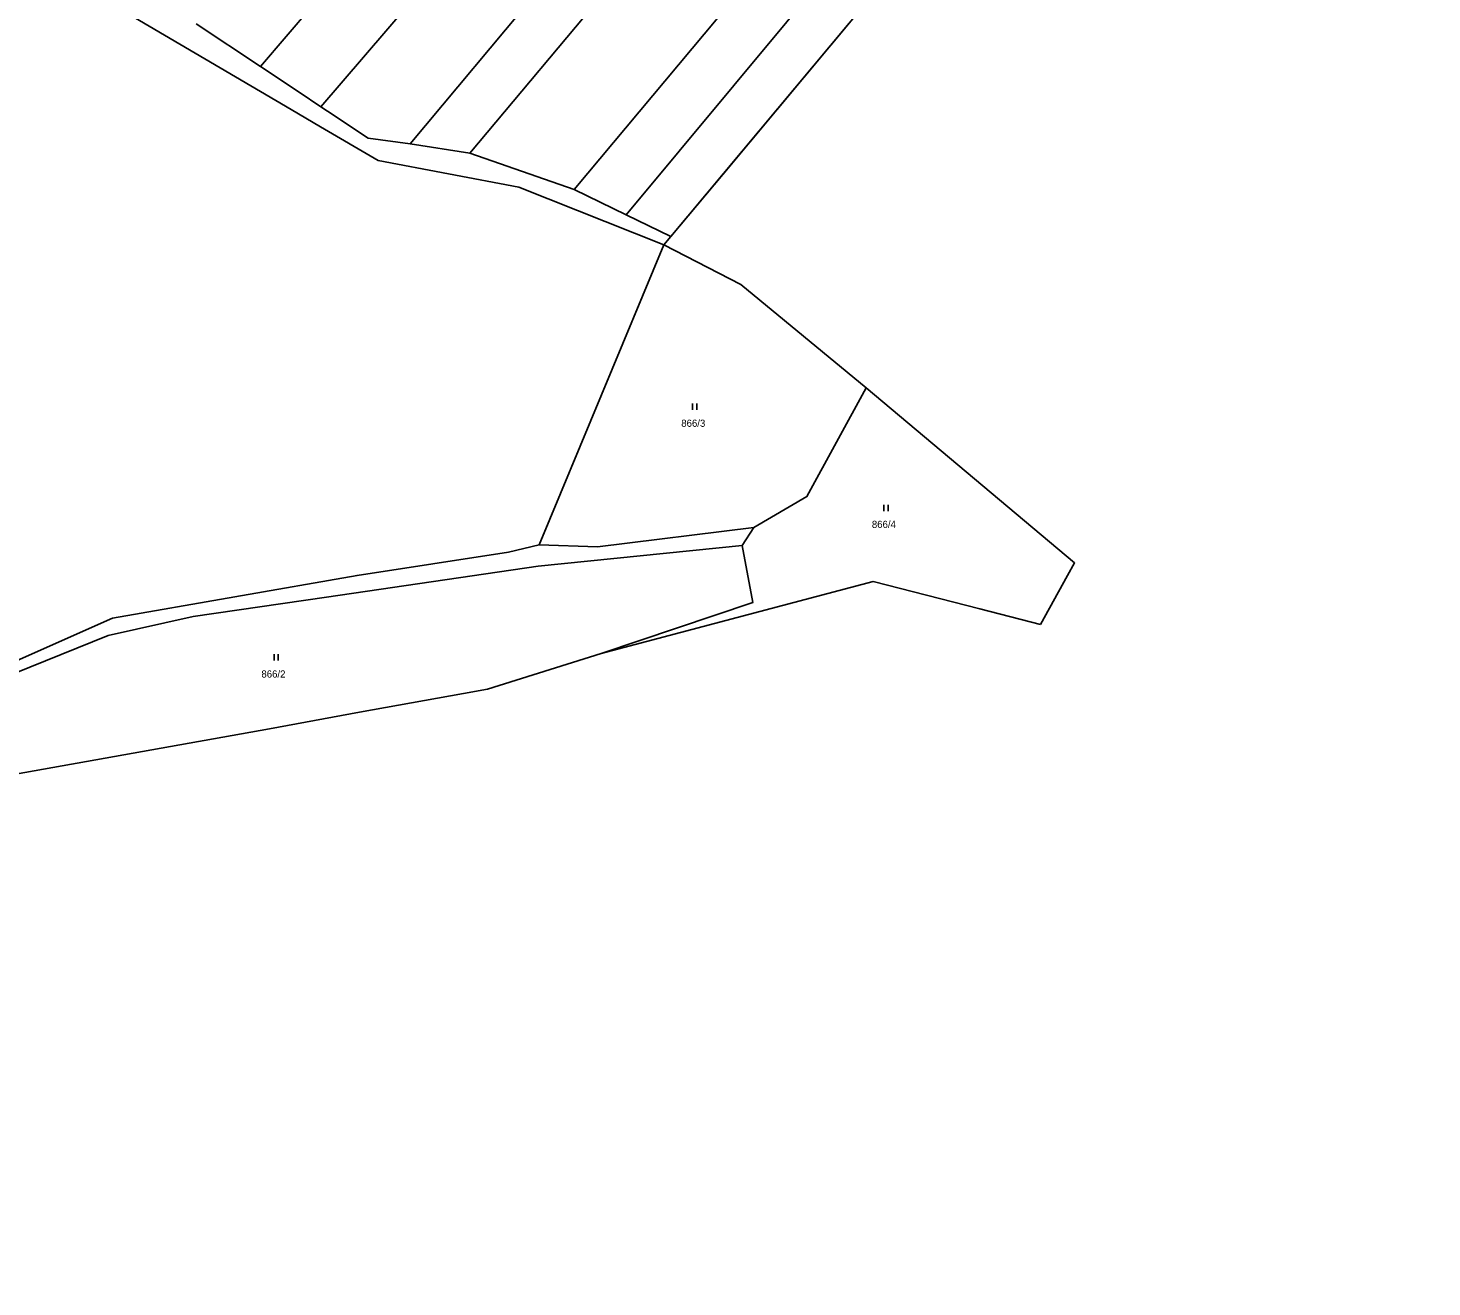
# Model space of a CAD drawing. Extents: x -7476540 to -746055, y -11317203 to -1129777.
# Drawn here: x -747223.3 to -746891.2, y -1132213.1 to -1131915.2 of the extents above; entities that cross this region are included whole.
import ezdxf

# ---------------------------------------------------------------- set-up
doc = ezdxf.new("R2010")
doc.units = 0
for name, color, linetype in [('Hranice parcel', 7, 'Continuous'), ('Parcelní čísla', 7, 'Continuous'), ('Vrstva 55', 7, 'Continuous'), ('Značky kultur', 7, 'Continuous')]:
    doc.layers.add(name, color=color, linetype=linetype)

msp = doc.modelspace()

# ---------------------------------------------------------------- linework, layer by layer
at = {"layer": 'Hranice parcel'}
for p, q in [((-747168.35, -1131924.28), (-747183.54, -1131914.17)), ((-747118.82, -1131944.76), (-747132.91, -1131942.59)), ((-747094.15, -1131953.41), (-747118.82, -1131944.76)), ((-747081.82, -1131959.38), (-747094.15, -1131953.41)), ((-747071.24, -1131964.51), (-747081.82, -1131959.38)), ((-747072.89, -1131966.47), (-747071.24, -1131964.51)), ((-747102.43, -1132037.5), (-747072.89, -1131966.47)), ((-747025.04, -1132000.35), (-747039.86, -1131988.12)), ((-747054.35, -1132037.66), (-747051.63, -1132033.4)), ((-746983.8, -1132056.28), (-746977.4, -1132044.75)), ((-746998.16, -1132052.61), (-746983.8, -1132056.28))]:
    msp.add_line(p, q, dxfattribs=at)
for points in [[(-747168.35, -1131924.28), (-747156.17, -1131910.12), (-747146.8, -1131899.23), (-747135.89, -1131886.55), (-747102.76, -1131847.44), (-747086.37, -1131828.14), (-747038.09, -1131772.55)], [(-747154.03, -1131933.81), (-747087.71, -1131856.54), (-747020.83, -1131778.66)], [(-747132.91, -1131942.59), (-747102.75, -1131906.39), (-747000.3, -1131785.93)], [(-746987.72, -1131790.65), (-747085.59, -1131905.13), (-747118.82, -1131944.76)], [(-747094.15, -1131953.41), (-747029.41, -1131875.97), (-746964.65, -1131799.29)], [(-747081.82, -1131959.38), (-747018.32, -1131883), (-746952.09, -1131804)], [(-747072.89, -1131966.47), (-747107.18, -1131952.81), (-747140.46, -1131946.56), (-747154.1, -1131938.56), (-747161.04, -1131934.49), (-747204.18, -1131909.18), (-747226.07, -1131896.73), (-747265.2, -1131885.54)], [(-747020.64, -1131903.85), (-747058.92, -1131949.83), (-747071.24, -1131964.51)], [(-747154.03, -1131933.81), (-747159.2, -1131930.37), (-747168.35, -1131924.28)], [(-747132.91, -1131942.59), (-747142.83, -1131941.27), (-747152.45, -1131934.86), (-747154.03, -1131933.81)], [(-747039.86, -1131988.12), (-747054.69, -1131975.89), (-747072.89, -1131966.47)], [(-747051.63, -1132033.4), (-747039.08, -1132026.03), (-747025.04, -1132000.35)], [(-746977.4, -1132044.75), (-746975.74, -1132041.76), (-747025.04, -1132000.35)], [(-747051.63, -1132033.4), (-747088.58, -1132037.93), (-747102.43, -1132037.5)], [(-747299.75, -1132213.05), (-747296.34, -1132200.82), (-747282.88, -1132149.41), (-747269.58, -1132097.49), (-747245.11, -1132073.4), (-747236.79, -1132069.7), (-747224.47, -1132064.21), (-747203.37, -1132054.82), (-747145.49, -1132044.7), (-747109.66, -1132039.16), (-747102.43, -1132037.5)], [(-747263.75, -1132103.85), (-747263.48, -1132094.73), (-747243.01, -1132076.52), (-747239.61, -1132074.64), (-747229.58, -1132069.12), (-747226.57, -1132067.9), (-747204.37, -1132058.93), (-747184.23, -1132054.46), (-747152.75, -1132049.88), (-747102.63, -1132042.55), (-747054.35, -1132037.66)], [(-747087.7, -1132063.18), (-747051.87, -1132051.13), (-747054.35, -1132037.66)], [(-747087.7, -1132063.18), (-747023.43, -1132046.16), (-746998.16, -1132052.61)], [(-747120.33, -1132072.66), (-747114.6, -1132071.63), (-747087.7, -1132063.18)], [(-747228.47, -1132092.15), (-747166.2, -1132081.01), (-747144.88, -1132077.08), (-747120.33, -1132072.66)]]:
    msp.add_lwpolyline(points, dxfattribs=at)
at = {"layer": 'Vrstva 55'}
msp.add_lwpolyline([(-746891.21, -1131727.46), (-746894.04, -1131732), (-746896.34, -1131736.09), (-746917.25, -1131771.33), (-746931.04, -1131793.38), (-746938.23, -1131804.89), (-746941.23, -1131808.49), (-747020.64, -1131903.85), (-747071.24, -1131964.51), (-747072.89, -1131966.47)], dxfattribs=at)
at = {"layer": 'Značky kultur'}
for p, q in [((-747066.1, -1132005.49), (-747066.1, -1132003.99)), ((-747065.1, -1132005.49), (-747065.1, -1132003.99)), ((-747020.85, -1132029.49), (-747020.85, -1132027.99)), ((-747019.85, -1132029.49), (-747019.85, -1132027.99)), ((-747165.13, -1132064.87), (-747165.13, -1132063.37)), ((-747164.13, -1132064.87), (-747164.13, -1132063.37))]:
    msp.add_line(p, q, dxfattribs=at)

# ---------------------------------------------------------------- texts
at = {"layer": 'Parcelní čísla'}
for s, p in [('866/3', (-747068.79, -1132009.54)), ('866/4', (-747023.7, -1132033.47)), ('866/2', (-747168.11, -1132068.87))]:
    msp.add_text(s, height=1.7, dxfattribs=at).set_placement(p)

doc.saveas('drawing.dxf')
